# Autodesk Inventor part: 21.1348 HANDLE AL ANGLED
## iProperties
Created: 2007-02
Part Number: 21.1348 HANDLE AL ANGLED
Document SubType Name: Modeling
Designer: Andy Moles
Material: Aluminum-6061
Mass: 45.4528 g
Surface Area: 75.1961 cm^2
Volume: 16.7722 cm^3
Density: 2.71 g/cm^3
Author: Andy Moles
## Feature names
1. Base1
2. Extrusion1
